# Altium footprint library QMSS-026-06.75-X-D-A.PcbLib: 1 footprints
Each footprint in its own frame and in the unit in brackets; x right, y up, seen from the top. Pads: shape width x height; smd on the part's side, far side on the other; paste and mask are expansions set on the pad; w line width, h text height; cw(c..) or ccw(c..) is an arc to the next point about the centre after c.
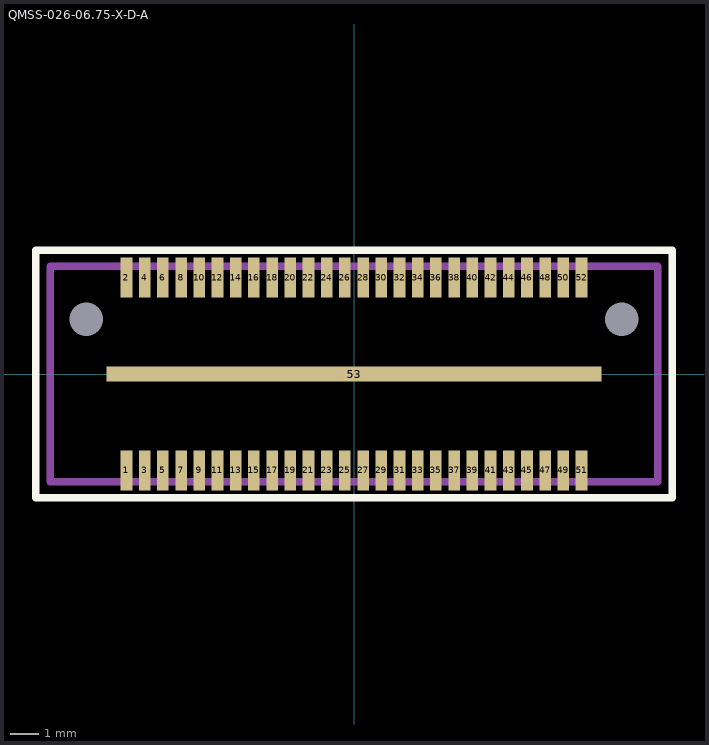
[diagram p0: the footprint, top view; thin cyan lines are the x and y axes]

## QMSS-026-06.75-X-D-A [mil]
pads (55):
  rect 16x55 smd mask+2: 1(-312.5,-132.5) 2(-312.5,132.5) 3(-287.5,-132.5) 4(-287.5,132.5) 5(-262.5,-132.5) 6(-262.5,132.5) 7(-237.5,-132.5) 8(-237.5,132.5) 9(-212.5,-132.5) 10(-212.5,132.5) 11(-187.5,-132.5) 12(-187.5,132.5) 13(-162.5,-132.5) 14(-162.5,132.5) 15(-137.5,-132.5) 16(-137.5,132.5) 17(-112.5,-132.5) 18(-112.5,132.5) 19(-87.5,-132.5) 20(-87.5,132.5) 21(-62.5,-132.5) 22(-62.5,132.5) 23(-37.5,-132.5) 24(-37.5,132.5) 25(-12.5,-132.5) 26(-12.5,132.5) 27(12.5,-132.5) 28(12.5,132.5) 29(37.5,-132.5) 30(37.5,132.5) 31(62.5,-132.5) 32(62.5,132.5) 33(87.5,-132.5) 34(87.5,132.5) 35(112.5,-132.5) 36(112.5,132.5) 37(137.5,-132.5) 38(137.5,132.5) 39(162.5,-132.5) 40(162.5,132.5) 41(187.5,-132.5) 42(187.5,132.5) 43(212.5,-132.5) 44(212.5,132.5) 45(237.5,-132.5) 46(237.5,132.5) 47(262.5,-132.5) 48(262.5,132.5) 49(287.5,-132.5) 50(287.5,132.5) 51(312.5,-132.5) 52(312.5,132.5)
  rect 680x20 smd mask+2: 53(0,0)
  round 0 hole 46 unplated: 54(-367.5,75) 55(367.5,75)
Top Overlay:
  lines w10: -437,-170 -437,170 437,170 437,-170 -437,-170
Mechanical 1:
  lines w10: -417,-148 -417,148 417,148 417,-148 -417,-148
  text "J1" at -17.57,-18 h30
